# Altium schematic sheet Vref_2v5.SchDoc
size A4
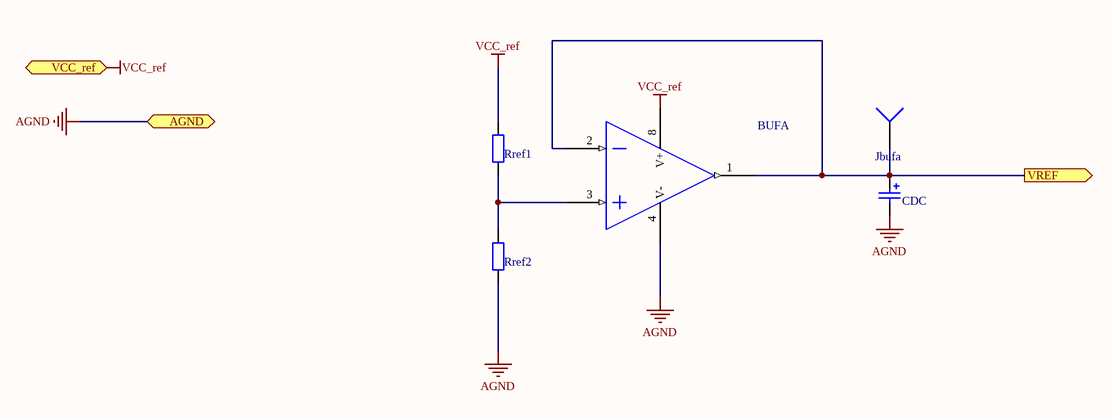
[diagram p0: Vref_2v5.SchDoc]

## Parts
BUF  LT6221  [ECE-SO8]  (value not drawn)  (part A of 2)
CDC  10uF  [ECE-CAPAE4X5.4SM]  (value not drawn)
Jbufa  TEST PIN  [ECE-HDR1TH]  (value not drawn)
Rref1  47K  [ECE-RESC1608-0603SM]  (value not drawn)
Rref2  47K  [ECE-RESC1608-0603SM]  (value not drawn)

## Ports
AGND (bidir), VCC_ref (in), VREF (out)

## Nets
AGND: BUF.4(V-) CDC.2 Rref2.1 ; port AGND
VCC_ref: BUF.8(V+) Rref1.2 ; port VCC_ref
VREF: BUF.1(OUT1) BUF.2(IN1(-)) CDC.1 Jbufa.1 ; port VREF
NetBUF_3: BUF.3(IN1(+)) Rref1.1 Rref2.2

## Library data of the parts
BUF = OPA000102: IC OPAMP LT6221 DUAL SM; Manufactuer: Linear Technology; Manufacturer-PN: LT6221CS8#TRPBF; Assembly Method: Surface Mount; Item Type: Item; Path: ece/ts/Lists/Stock Inventory
CDC = CAP000303: CAP 10uF 16V ELE SM; Manufactuer: Nichicon; Manufacturer-PN: UWT1C100MCL1GB; Assembly Method: Surface Mount; Item Type: Item; Path: ece/ts/Lists/Stock Inventory
Jbufa = CON000017: Value: 1 way; Assembly Method: Through hole; Item Type: Item; Path: ece/ts/Lists/Stock Inventory
Rref1 Rref2 = RES000158: RES CER 47K 1608 SM; Manufactuer: Yageo; Manufacturer-PN: RC0603FR-0747KL; Assembly Method: Surface Mount; Voltage/Current: 1/10W; Item Type: Item; Path: ece/ts/Lists/Stock Inventory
